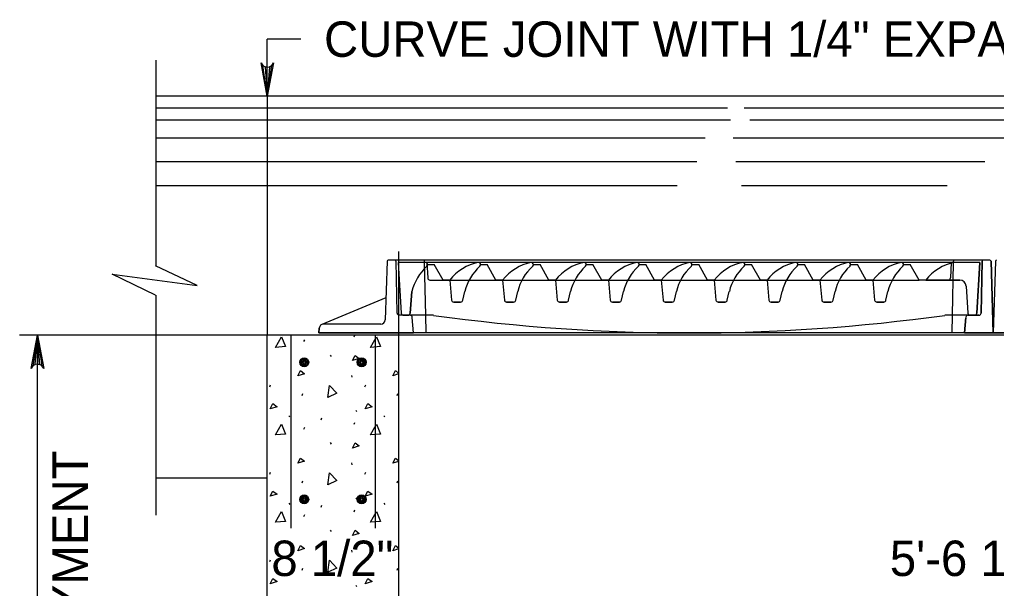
# Model space of a CAD drawing. Extents: x 6.91 to 13.84, y 0.35 to 9.99.
# Drawn here: x 6.977 to 8.632, y 6.754 to 7.719 of the extents above; entities that cross this region are included whole.
import ezdxf

# ---------------------------------------------------------------- set-up
doc = ezdxf.new("R2010")
doc.units = 0
for name, color, linetype in [('DETL-DIMS', 7, 'Continuous'), ('DETL-LINE', 7, 'Continuous'), ('DETL-NOTE', 7, 'Continuous'), ('DETL-PATT', 7, 'Continuous')]:
    doc.layers.add(name, color=color, linetype=linetype)

msp = doc.modelspace()

# ---------------------------------------------------------------- linework, layer by layer
at = {"layer": 'DETL-DIMS'}
for p, q in [((7.4531, 7.6854), (7.3965, 7.6854)), ((7.3965, 7.5885), (7.3965, 7.6854)), ((7.4781, 7.1839), (6.9766, 7.1839)), ((7.0069, 5.9311), (7.0069, 7.1839))]:
    msp.add_line(p, q, dxfattribs=at)
for points in [[(7.3965, 7.5885), (7.3859, 7.645), (7.3889, 7.6407), (7.3927, 7.6384), (7.3965, 7.6378), (7.4003, 7.6384), (7.4041, 7.6407), (7.4071, 7.645), (7.3965, 7.5885), (7.4041, 7.6407), (7.4003, 7.6384), (7.3965, 7.5885), (7.3965, 7.6378), (7.3927, 7.6384), (7.3965, 7.5885), (7.3889, 7.6407)], [(7.0069, 7.1839), (7.0175, 7.1274), (7.0145, 7.1317), (7.0107, 7.134), (7.0069, 7.1346), (7.0031, 7.134), (6.9993, 7.1317), (6.9963, 7.1274), (7.0069, 7.1839), (6.9993, 7.1317), (7.0031, 7.134), (7.0069, 7.1839), (7.0069, 7.1346), (7.0107, 7.134), (7.0069, 7.1839), (7.0145, 7.1317)]]:
    msp.add_lwpolyline(points, dxfattribs=at)
at = {"layer": 'DETL-LINE'}
for p, q in [((7.2076, 7.6498), (7.2076, 7.3013)), ((7.3965, 7.5885), (7.2076, 7.5885)), ((9.864, 7.5885), (7.3965, 7.5885)), ((7.3965, 7.5885), (7.3965, 7.1839)), ((7.619, 7.3255), (7.619, 5.8086)), ((7.5995, 7.3089), (7.5965, 7.2096)), ((7.5995, 7.3089), (7.5965, 7.2096)), ((8.6211, 7.3107), (7.6014, 7.3107)), ((7.6127, 7.3107), (7.6014, 7.3107)), ((7.6163, 7.221), (7.6146, 7.3089)), ((7.6163, 7.221), (7.6146, 7.3089)), ((7.6631, 7.307), (7.6631, 7.3089)), ((7.6649, 7.2173), (7.6631, 7.307)), ((7.6668, 7.307), (7.6684, 7.2806)), ((8.5557, 7.307), (8.5541, 7.2806)), ((8.5576, 7.2173), (8.5594, 7.3067)), ((8.5594, 7.307), (8.5594, 7.3089)), ((8.6043, 7.307), (8.5608, 7.307)), ((8.5989, 7.2208), (8.6043, 7.307)), ((8.6062, 7.221), (8.608, 7.3089)), ((8.608, 7.3089), (8.6062, 7.221)), ((8.6211, 7.3107), (8.6098, 7.3107)), ((8.623, 7.3089), (8.6267, 7.1875)), ((8.6304, 7.3089), (8.6267, 7.1875)), ((7.6721, 7.2771), (8.5011, 7.2771)), ((7.7056, 7.2771), (7.7087, 7.2431)), ((7.7952, 7.2771), (7.7983, 7.2431)), ((7.8849, 7.2771), (7.888, 7.2431)), ((7.9745, 7.2771), (7.9776, 7.2431)), ((8.0641, 7.2771), (8.0673, 7.2431)), ((8.1538, 7.2771), (8.1569, 7.2431)), ((8.2434, 7.2771), (8.2465, 7.2431)), ((8.3331, 7.2771), (8.3362, 7.2431)), ((8.4227, 7.2771), (8.4258, 7.2431)), ((8.5123, 7.2771), (8.5699, 7.2771)), ((7.6385, 7.2208), (7.6416, 7.2576)), ((7.7279, 7.2432), (7.7312, 7.2576)), ((7.8175, 7.2432), (7.8209, 7.2576)), ((7.9071, 7.2432), (7.9105, 7.2576)), ((7.9968, 7.2432), (8.0002, 7.2576)), ((8.0864, 7.2432), (8.0898, 7.2576)), ((8.1761, 7.2432), (8.1794, 7.2576)), ((8.2657, 7.2432), (8.2691, 7.2576)), ((8.3553, 7.2432), (8.3587, 7.2576)), ((8.445, 7.2432), (8.4483, 7.2576)), ((8.5811, 7.2666), (8.5839, 7.2208)), ((7.2076, 7.2512), (7.2076, 6.8784)), ((7.5976, 7.2472), (7.4891, 7.2018)), ((7.7124, 7.2397), (7.7241, 7.2397)), ((7.8021, 7.2397), (7.8138, 7.2397)), ((7.8917, 7.2397), (7.9034, 7.2397)), ((7.9813, 7.2397), (7.9931, 7.2397)), ((8.071, 7.2397), (8.0827, 7.2397)), ((8.1606, 7.2397), (8.1723, 7.2397)), ((8.2502, 7.2397), (8.262, 7.2397)), ((8.3399, 7.2397), (8.3516, 7.2397)), ((8.4295, 7.2397), (8.4412, 7.2397)), ((7.589, 7.2024), (7.4919, 7.2024)), ((7.589, 7.2024), (7.4919, 7.2024)), ((7.6384, 7.2173), (7.6201, 7.2173)), ((7.6273, 7.2173), (7.6348, 7.2173)), ((7.6444, 7.1875), (7.6421, 7.2139)), ((7.6655, 7.1875), (7.6649, 7.2173)), ((8.557, 7.1875), (8.5576, 7.2173)), ((8.5781, 7.1875), (8.5804, 7.2139)), ((8.5842, 7.2173), (8.6025, 7.2173)), ((8.5876, 7.2173), (8.5842, 7.2173)), ((8.5876, 7.2173), (8.5951, 7.2173)), ((8.6025, 7.2173), (8.5877, 7.2173)), ((7.4838, 7.1875), (7.4845, 7.1956)), ((8.6267, 7.1875), (7.4838, 7.1875)), ((9.7695, 7.1875), (8.6267, 7.1875)), ((9.864, 7.1839), (7.3965, 7.1839)), ((7.3965, 6.3999), (7.3965, 7.1839)), ((7.4362, 7.1839), (7.4362, 6.8566)), ((7.4585, 7.1727), (7.4601, 7.1759)), ((7.5434, 7.1807), (7.5447, 7.1839)), ((7.5793, 7.1839), (7.5793, 6.8566)), ((7.5032, 7.1497), (7.5048, 7.1473)), ((7.5394, 7.1155), (7.5398, 7.1123)), ((7.619, 7.1179), (7.6091, 7.1147)), ((7.4009, 7.0962), (7.4021, 7.0994)), ((7.562, 7.0962), (7.5632, 7.0994)), ((7.4553, 7.0817), (7.4565, 7.0849)), ((7.6163, 7.0817), (7.6175, 7.0849)), ((7.5463, 7.0563), (7.5475, 7.0543)), ((7.4331, 7.0471), (7.4348, 7.0451)), ((7.4875, 7.0402), (7.4891, 7.0434)), ((7.5942, 7.0471), (7.5958, 7.0451)), ((7.4585, 7.0245), (7.4601, 7.0277)), ((7.5434, 7.0326), (7.5447, 7.0358)), ((7.5032, 7.0016), (7.5048, 6.9992)), ((7.5394, 6.9674), (7.5398, 6.9641)), ((7.619, 6.9697), (7.6091, 6.9666)), ((7.3965, 6.9412), (7.2076, 6.9412)), ((7.4009, 6.948), (7.4021, 6.9513)), ((7.562, 6.948), (7.5632, 6.9513)), ((7.4553, 6.9335), (7.4565, 6.9368)), ((7.6163, 6.9335), (7.6175, 6.9368)), ((7.5463, 6.9082), (7.5475, 6.9062)), ((7.4331, 6.8989), (7.4348, 6.8969)), ((7.4875, 6.8921), (7.4891, 6.8953)), ((7.5434, 6.8844), (7.5447, 6.8877)), ((7.5942, 6.8989), (7.5958, 6.8969)), ((7.4585, 6.8764), (7.4601, 6.8796)), ((7.5032, 6.8534), (7.5048, 6.851)), ((7.619, 6.8216), (7.6091, 6.8184)), ((7.5394, 6.8192), (7.5398, 6.816)), ((7.4009, 6.7999), (7.4021, 6.8031)), ((7.4553, 6.7854), (7.4565, 6.7886)), ((7.562, 6.7999), (7.5632, 6.8031)), ((7.6163, 6.7854), (7.6175, 6.7886)), ((7.5463, 6.76), (7.5475, 6.758))]:
    msp.add_line(p, q, dxfattribs=at)
for points in [[(7.6644, 7.307), (7.6182, 7.307), (7.6236, 7.2208)], [(8.5804, 7.2139), (8.5781, 7.1875), (8.6267, 7.1875), (8.623, 7.3089)], [(8.6304, 7.3089), (8.6267, 7.1875), (8.6752, 7.1875), (8.6729, 7.2139)], [(7.2071, 7.2512), (7.1334, 7.2873), (7.2777, 7.2677), (7.2071, 7.3013)], [(7.4845, 7.1956), (7.4838, 7.1875), (7.6444, 7.1875), (7.6421, 7.2139)], [(7.6384, 7.2173), (7.6348, 7.2173), (7.6273, 7.2173), (7.6201, 7.2173)], [(7.4106, 7.163), (7.4203, 7.1811), (7.4275, 7.1642), (7.4106, 7.163)], [(7.5716, 7.163), (7.5813, 7.1811), (7.5885, 7.1642), (7.5716, 7.163)], [(7.541, 7.1405), (7.5451, 7.1493), (7.5523, 7.1441), (7.541, 7.1405)], [(7.448, 7.1147), (7.4525, 7.1236), (7.4593, 7.1183), (7.448, 7.1147)], [(7.6091, 7.1147), (7.6135, 7.1236), (7.619, 7.1194)], [(7.4988, 7.0781), (7.5016, 7.0986), (7.5141, 7.0853), (7.4988, 7.0781)], [(7.4013, 7.0587), (7.4058, 7.0676), (7.413, 7.0624), (7.4013, 7.0587)], [(7.5624, 7.0587), (7.5668, 7.0676), (7.574, 7.0624), (7.5624, 7.0587)], [(7.4106, 7.0149), (7.4203, 7.033), (7.4275, 7.0161), (7.4106, 7.0149)], [(7.5716, 7.0149), (7.5813, 7.033), (7.5885, 7.0161), (7.5716, 7.0149)], [(7.541, 6.9923), (7.5451, 7.0012), (7.5523, 6.9959), (7.541, 6.9923)], [(7.448, 6.9666), (7.4525, 6.9754), (7.4593, 6.9702), (7.448, 6.9666)], [(7.6091, 6.9666), (7.6135, 6.9754), (7.619, 6.9712)], [(7.4988, 6.9299), (7.5016, 6.9505), (7.5141, 6.9372), (7.4988, 6.9299)], [(7.4013, 6.9106), (7.4058, 6.9195), (7.413, 6.9142), (7.4013, 6.9106)], [(7.5624, 6.9106), (7.5668, 6.9195), (7.574, 6.9142), (7.5624, 6.9106)], [(7.4106, 6.8667), (7.4203, 6.8848), (7.4275, 6.8679), (7.4106, 6.8667)], [(7.5716, 6.8667), (7.5813, 6.8848), (7.5885, 6.8679), (7.5716, 6.8667)], [(7.541, 6.8442), (7.5451, 6.853), (7.5523, 6.8478), (7.541, 6.8442)], [(7.448, 6.8184), (7.4525, 6.8273), (7.4593, 6.822), (7.448, 6.8184)], [(7.6091, 6.8184), (7.6135, 6.8273), (7.619, 6.8231)], [(7.4988, 6.7818), (7.5016, 6.8023), (7.5141, 6.789), (7.4988, 6.7818)], [(7.4013, 6.7625), (7.4058, 6.7713), (7.413, 6.7661), (7.4013, 6.7625)], [(7.5624, 6.7625), (7.5668, 6.7713), (7.574, 6.7661), (7.5624, 6.7625)]]:
    msp.add_lwpolyline(points, dxfattribs=at)
for centre, radius in [((7.459, 7.1377), 0.00758), ((7.459, 7.1377), 0.00569), ((7.459, 7.1377), 0.00379), ((7.459, 7.1377), 0.0019), ((7.5565, 7.1377), 0.00758), ((7.5565, 7.1377), 0.00569), ((7.5565, 7.1377), 0.00379), ((7.5565, 7.1377), 0.0019), ((7.459, 6.9053), 0.00758), ((7.459, 6.9053), 0.00569), ((7.459, 6.9053), 0.00379), ((7.459, 6.9053), 0.0019), ((7.5565, 6.9053), 0.00758), ((7.5565, 6.9053), 0.00569), ((7.5565, 6.9053), 0.00379), ((7.5565, 6.9053), 0.0019)]:
    msp.add_circle(centre, radius, dxfattribs=at)
for centre, radius, start, end in [((7.6014, 7.3088), 0.00187, 90, 178.2145), ((7.6014, 7.3088), 0.00187, 90, 178.2145), ((7.6127, 7.3088), 0.00187, 1.1458, 90), ((7.6127, 7.3088), 0.00187, 1.1458, 90), ((7.6612, 7.3088), 0.00187, 1.1222, 90), ((7.6644, 7.3032), 0.00373, 312.139, 90), ((7.771, 7.2253), 0.0834, 101.6847, 141.6027), ((7.7541, 7.3032), 0.00373, 312.139, 90), ((7.8606, 7.2253), 0.0834, 101.6847, 141.6027), ((7.8437, 7.3032), 0.00373, 312.139, 90), ((7.9502, 7.2253), 0.0834, 101.6847, 141.6027), ((7.9333, 7.3032), 0.00373, 312.139, 90), ((8.0399, 7.2253), 0.0834, 101.6847, 141.6027), ((8.023, 7.3032), 0.00373, 312.139, 90), ((8.1295, 7.2253), 0.0834, 101.6847, 141.6027), ((8.1126, 7.3032), 0.00373, 312.139, 90), ((8.2192, 7.2253), 0.0834, 101.6847, 141.6027), ((8.2023, 7.3032), 0.00373, 312.139, 90), ((8.3088, 7.2253), 0.0834, 101.6847, 141.6027), ((8.2919, 7.3032), 0.00373, 312.139, 90), ((8.3984, 7.2253), 0.0834, 101.6847, 141.6027), ((8.3815, 7.3032), 0.00373, 312.139, 90), ((8.4881, 7.2253), 0.0834, 101.6847, 141.6027), ((8.4712, 7.3032), 0.00373, 312.139, 90), ((8.5777, 7.2253), 0.0834, 101.6847, 141.6027), ((8.5613, 7.3088), 0.00187, 90, 178.8778), ((8.6098, 7.3088), 0.00187, 90, 178.8542), ((8.6098, 7.3088), 0.00187, 90, 178.8542), ((8.6211, 7.3088), 0.00187, 1.7855, 90), ((8.6211, 7.3088), 0.00187, 1.7855, 90), ((8.6322, 7.3088), 0.00187, 90, 178.2145), ((8.6322, 7.3088), 0.00187, 90, 178.2145), ((7.7228, 7.2385), 0.0834, 132.0547, 166.7971), ((7.8125, 7.2385), 0.0834, 132.0547, 166.7971), ((7.9021, 7.2385), 0.0834, 132.0547, 166.7971), ((7.9917, 7.2385), 0.0834, 132.0547, 166.7971), ((8.0814, 7.2385), 0.0834, 132.0547, 166.7971), ((8.171, 7.2385), 0.0834, 132.0547, 166.7971), ((8.2607, 7.2385), 0.0834, 132.0547, 166.7971), ((8.3503, 7.2385), 0.0834, 132.0547, 166.7971), ((8.4399, 7.2385), 0.0834, 132.0547, 166.7971), ((8.5296, 7.2385), 0.0834, 132.0547, 166.7971), ((7.6721, 7.2808), 0.00373, 183.5874, 270.0007), ((8.5504, 7.2808), 0.00373, 269.9993, 356.4126), ((8.5699, 7.2659), 0.0112, 3.5763, 89.9993), ((7.7124, 7.2435), 0.00373, 186.5049, 270), ((7.7241, 7.2435), 0.00373, 270, 356.0265), ((7.8021, 7.2435), 0.00373, 186.5049, 270), ((7.8138, 7.2435), 0.00373, 270, 356.0265), ((7.8917, 7.2435), 0.00373, 186.5049, 270), ((7.9034, 7.2435), 0.00373, 270, 356.0265), ((7.9813, 7.2435), 0.00373, 186.5049, 270), ((7.9931, 7.2435), 0.00373, 270, 356.0265), ((8.071, 7.2435), 0.00373, 186.5049, 270), ((8.0827, 7.2435), 0.00373, 270, 356.0265), ((8.1606, 7.2435), 0.00373, 186.5049, 270), ((8.1723, 7.2435), 0.00373, 270, 356.0265), ((8.2502, 7.2435), 0.00373, 186.5049, 270), ((8.262, 7.2435), 0.00373, 270, 356.0265), ((8.3399, 7.2435), 0.00373, 186.5049, 270), ((8.3516, 7.2435), 0.00373, 270, 356.0265), ((8.4295, 7.2435), 0.00373, 186.5049, 270), ((8.4412, 7.2435), 0.00373, 270, 356.0265), ((7.6201, 7.2211), 0.00373, 181.1458, 270), ((7.6201, 7.2211), 0.00373, 181.1458, 270), ((7.6273, 7.2211), 0.00373, 183.5616, 270), ((7.6348, 7.2211), 0.00373, 270, 355.2441), ((8.5876, 7.2211), 0.00373, 183.5763, 268.8729), ((8.5951, 7.2211), 0.00373, 270, 356.4126), ((8.6025, 7.2211), 0.00373, 270, 358.8542), ((8.6025, 7.2211), 0.00373, 270, 358.8542), ((7.4919, 7.1949), 0.00747, 90, 175), ((7.4919, 7.1949), 0.00747, 90, 175), ((7.589, 7.2099), 0.00747, 270, 358.2584), ((7.589, 7.2099), 0.00747, 270, 358.2584), ((7.6384, 7.2136), 0.00373, 5, 90), ((7.6384, 7.2136), 0.00373, 5, 90), ((8.5842, 7.2136), 0.00373, 90, 175), ((8.5842, 7.2136), 0.00373, 90, 175), ((8.5876, 7.2211), 0.00373, 268.8729, 271.1271)]:
    msp.add_arc(centre, radius, start, end, dxfattribs=at)
at = {"layer": 'DETL-NOTE'}
for p, q in [((7.5996, 7.3107), (7.5996, 7.3107)), ((7.6145, 7.3107), (7.6145, 7.3107)), ((7.6145, 7.3107), (7.6145, 7.3107)), ((8.6043, 7.307), (7.6182, 7.307)), ((7.6182, 7.307), (7.6236, 7.2208)), ((7.6182, 7.307), (7.6182, 7.307)), ((7.6682, 7.3032), (7.6794, 7.3032)), ((7.6944, 7.2771), (7.6794, 7.3032)), ((7.7578, 7.3032), (7.769, 7.3032)), ((7.784, 7.2771), (7.769, 7.3032)), ((7.8474, 7.3032), (7.8587, 7.3032)), ((7.8737, 7.2771), (7.8587, 7.3032)), ((7.9371, 7.3032), (7.9483, 7.3032)), ((7.9633, 7.2771), (7.9483, 7.3032)), ((8.0267, 7.3032), (8.0379, 7.3032)), ((8.0529, 7.2771), (8.0379, 7.3032)), ((8.1164, 7.3032), (8.1276, 7.3032)), ((8.1426, 7.2771), (8.1276, 7.3032)), ((8.206, 7.3032), (8.2172, 7.3032)), ((8.2322, 7.2771), (8.2172, 7.3032)), ((8.2956, 7.3032), (8.3068, 7.3032)), ((8.3218, 7.2771), (8.3068, 7.3032)), ((8.3853, 7.3032), (8.3965, 7.3032)), ((8.4115, 7.2771), (8.3965, 7.3032)), ((8.4749, 7.3032), (8.4861, 7.3032)), ((8.5011, 7.2771), (8.4861, 7.3032)), ((8.6043, 7.307), (8.5989, 7.2208)), ((8.6043, 7.307), (8.6043, 7.307)), ((8.608, 7.3107), (8.608, 7.3107)), ((8.6304, 7.3107), (8.6304, 7.3107)), ((7.7056, 7.2771), (7.6944, 7.2771)), ((7.7056, 7.2771), (7.7087, 7.2432)), ((7.7952, 7.2771), (7.784, 7.2771)), ((7.7952, 7.2771), (7.7983, 7.2432)), ((7.8849, 7.2771), (7.8737, 7.2771)), ((7.8849, 7.2771), (7.888, 7.2432)), ((7.9745, 7.2771), (7.9633, 7.2771)), ((7.9745, 7.2771), (7.9776, 7.2432)), ((8.0641, 7.2771), (8.0529, 7.2771)), ((8.0641, 7.2771), (8.0672, 7.2432)), ((8.1538, 7.2771), (8.1426, 7.2771)), ((8.1538, 7.2771), (8.1569, 7.2432)), ((8.2434, 7.2771), (8.2322, 7.2771)), ((8.2434, 7.2771), (8.2465, 7.2432)), ((8.3331, 7.2771), (8.3218, 7.2771)), ((8.3331, 7.2771), (8.3362, 7.2432)), ((8.4227, 7.2771), (8.4115, 7.2771)), ((8.4227, 7.2771), (8.4258, 7.2432)), ((8.5123, 7.2771), (8.5011, 7.2771)), ((8.5699, 7.2771), (8.5123, 7.2771)), ((7.6416, 7.2576), (7.6385, 7.2208)), ((7.7279, 7.2432), (7.7312, 7.2576)), ((7.8175, 7.2432), (7.8209, 7.2576)), ((7.9071, 7.2432), (7.9105, 7.2576)), ((7.9968, 7.2432), (8.0002, 7.2576)), ((8.0864, 7.2432), (8.0898, 7.2576)), ((8.1761, 7.2432), (8.1794, 7.2576)), ((8.2657, 7.2432), (8.2691, 7.2576)), ((8.3553, 7.2432), (8.3587, 7.2576)), ((8.445, 7.2432), (8.4483, 7.2576)), ((8.5811, 7.2666), (8.5839, 7.2208)), ((7.7241, 7.2397), (7.7124, 7.2397)), ((7.8138, 7.2397), (7.8021, 7.2397)), ((7.9034, 7.2397), (7.8917, 7.2397)), ((7.9931, 7.2397), (7.9813, 7.2397)), ((8.0827, 7.2397), (8.071, 7.2397)), ((8.1723, 7.2397), (8.1606, 7.2397)), ((8.262, 7.2397), (8.2502, 7.2397)), ((8.3516, 7.2397), (8.3399, 7.2397)), ((8.4412, 7.2397), (8.4295, 7.2397)), ((7.6348, 7.2173), (7.6273, 7.2173)), ((7.678, 7.2173), (7.6348, 7.2173)), ((8.5876, 7.2173), (8.5445, 7.2173)), ((8.5951, 7.2173), (8.5876, 7.2173)), ((7.4838, 7.1875), (7.4838, 7.1875)), ((7.6444, 7.1875), (7.6444, 7.1875)), ((8.5781, 7.1875), (8.5781, 7.1875)), ((8.6267, 7.1875), (8.6267, 7.1875))]:
    msp.add_line(p, q, dxfattribs=at)
for centre, radius, start, end in [((7.6644, 7.3032), 0.00373, 312.139, 90), ((7.771, 7.2253), 0.0834, 101.6847, 141.6027), ((7.7541, 7.3032), 0.00373, 312.139, 90), ((7.8606, 7.2253), 0.0834, 101.6847, 141.6027), ((7.8437, 7.3032), 0.00373, 312.139, 90), ((7.9502, 7.2253), 0.0834, 101.6847, 141.6027), ((7.9333, 7.3032), 0.00373, 312.139, 90), ((8.0399, 7.2253), 0.0834, 101.6847, 141.6027), ((8.023, 7.3032), 0.00373, 312.139, 90), ((8.1295, 7.2253), 0.0834, 101.6847, 141.6027), ((8.1126, 7.3032), 0.00373, 312.139, 90), ((8.2192, 7.2253), 0.0834, 101.6847, 141.6027), ((8.2023, 7.3032), 0.00373, 312.139, 90), ((8.3088, 7.2253), 0.0834, 101.6847, 141.6027), ((8.2919, 7.3032), 0.00373, 312.139, 90), ((8.3984, 7.2253), 0.0834, 101.6847, 141.6027), ((8.3815, 7.3032), 0.00373, 312.139, 90), ((8.4881, 7.2253), 0.0834, 101.6847, 141.6027), ((8.4712, 7.3032), 0.00373, 312.139, 90), ((8.5777, 7.2253), 0.0834, 101.6847, 141.6027), ((7.7228, 7.2385), 0.0834, 132.0547, 166.7971), ((7.8125, 7.2385), 0.0834, 132.0547, 166.7971), ((7.9021, 7.2385), 0.0834, 132.0547, 166.7971), ((7.9917, 7.2385), 0.0834, 132.0547, 166.7971), ((8.0814, 7.2385), 0.0834, 132.0547, 166.7971), ((8.171, 7.2385), 0.0834, 132.0547, 166.7971), ((8.2607, 7.2385), 0.0834, 132.0547, 166.7971), ((8.3503, 7.2385), 0.0834, 132.0547, 166.7971), ((8.4399, 7.2385), 0.0834, 132.0547, 166.7971), ((8.5296, 7.2385), 0.0834, 132.0547, 166.7971), ((8.5699, 7.2659), 0.0112, 3.5763, 90), ((7.7124, 7.2435), 0.00373, 183.9735, 270), ((7.7241, 7.2435), 0.00373, 270, 356.0265), ((7.8021, 7.2435), 0.00373, 183.9735, 270), ((7.8138, 7.2435), 0.00373, 270, 356.0265), ((7.8917, 7.2435), 0.00373, 183.9735, 270), ((7.9034, 7.2435), 0.00373, 270, 356.0265), ((7.9813, 7.2435), 0.00373, 183.9735, 270), ((7.9931, 7.2435), 0.00373, 270, 356.0265), ((8.071, 7.2435), 0.00373, 183.9735, 270), ((8.0827, 7.2435), 0.00373, 270, 356.0265), ((8.1606, 7.2435), 0.00373, 183.9735, 270), ((8.1723, 7.2435), 0.00373, 270, 356.0265), ((8.2502, 7.2435), 0.00373, 183.9735, 270), ((8.262, 7.2435), 0.00373, 270, 356.0265), ((8.3399, 7.2435), 0.00373, 183.9735, 270), ((8.3516, 7.2435), 0.00373, 270, 356.0265), ((8.4295, 7.2435), 0.00373, 183.9735, 270), ((8.4412, 7.2435), 0.00373, 270, 356.0265), ((7.6273, 7.2211), 0.00373, 183.5616, 270), ((7.6348, 7.2211), 0.00373, 270, 355.2441), ((8.5876, 7.2211), 0.00373, 183.5763, 270), ((8.5951, 7.2211), 0.00373, 270, 356.4126), ((8.1113, 10.3434), 3.156, 262.1096, 277.8904)]:
    msp.add_arc(centre, radius, start, end, dxfattribs=at)
at = {"layer": 'DETL-PATT'}
for p, q in [((8.1765, 7.5682), (7.2076, 7.5682)), ((10.1347, 7.5682), (8.2049, 7.5682)), ((8.1812, 7.548), (7.2076, 7.548)), ((8.6759, 7.548), (8.2144, 7.548)), ((8.1386, 7.5177), (7.2076, 7.5177)), ((8.6517, 7.5177), (8.186, 7.5177)), ((8.1244, 7.4772), (7.2076, 7.4772)), ((8.6124, 7.4772), (8.1907, 7.4772)), ((8.0912, 7.4368), (7.2076, 7.4368)), ((8.5488, 7.4368), (8.2002, 7.4368))]:
    msp.add_line(p, q, dxfattribs=at)

# ---------------------------------------------------------------- texts
at = {"layer": 'DETL-NOTE'}
for s, p in [('CURVE JOINT WITH 1/4" EXPANSION MATERIAL', (7.4926, 7.6554)), ('8 1/2"', (7.4033, 6.7755)), ('5\'-6 1/2"', (8.4515, 6.7755))]:
    msp.add_text(s, height=0.06, dxfattribs=at).set_placement(p)
msp.add_text('DEPTH PAYMENT', height=0.06, rotation=90, dxfattribs=at).set_placement((7.0924, 6.3061))

doc.saveas('drawing.dxf')
